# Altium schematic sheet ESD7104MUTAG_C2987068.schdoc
size 127 x 101 mm
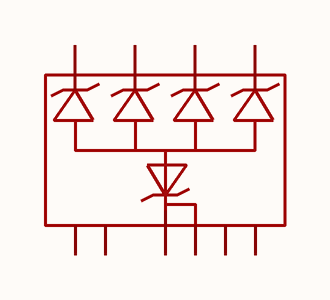
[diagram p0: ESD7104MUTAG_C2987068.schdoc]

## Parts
U?  esd7104mutag_c2987068  [DFN-10_L2.5-W1.0-P0.50-BL]  (value not drawn)

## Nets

Not connected (* = marked no-connect by the designer): U? 1 2 3 4 5 6(NC) 7(NC) 8 9(NC) 10(NC)

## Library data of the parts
U? = esd7104mutag_c2987068: Manufacturer: TECH PUBLIC(台舟); AddInBom: yes; ModelId: 55525fa8fc914f7c8ffcb10749ea5f73; ModelName: DFN-10_L2.5-W1.0-H0.5-P0.50; ModelTransform: 39.37,96.494,0,90,0,0,0.004,0.009,0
